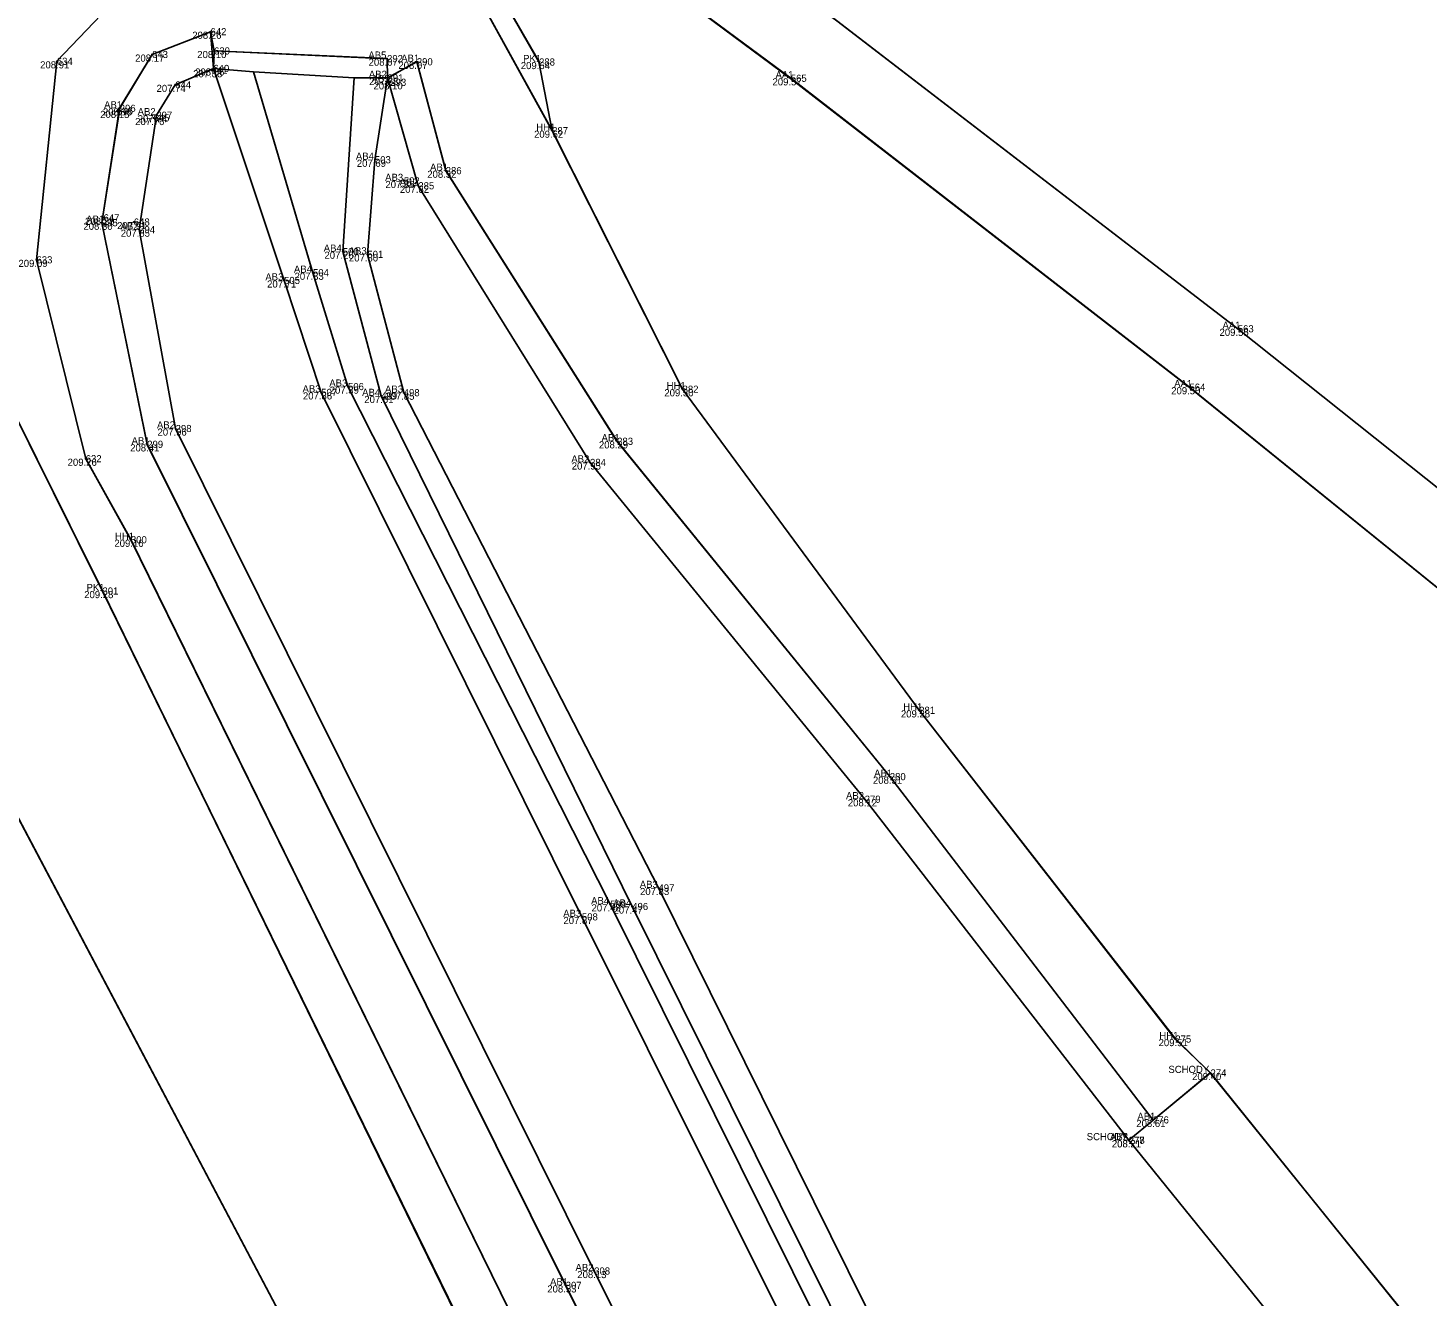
# Model space of a CAD drawing. Extents: x -262982 to -262706, y -1238714 to -1237093.
# Drawn here: x -262950.29 to -262911.03, y -1238449.49 to -1238413.92 of the extents above; entities that cross this region are included whole.
import ezdxf

# ---------------------------------------------------------------- set-up
doc = ezdxf.new("R2010")
doc.units = 0
for name, color, linetype in [('01_Hrana_betónu', 7, 'Continuous'), ('02_Oplotenie', 7, 'Continuous'), ('03_Asfalt', 7, 'Continuous'), ('05_Hrana_terénu', 7, 'Continuous'), ('06_Schody', 7, 'Continuous'), ('07_Iné', 7, 'Continuous'), ('10', 7, 'Continuous'), ('Groma (21)', 7, 'Continuous'), ('Groma (22)', 7, 'Continuous'), ('Groma (23)', 7, 'Continuous'), ('Groma (24)', 7, 'Continuous'), ('U001_Betónové_panely', 7, 'Continuous'), ('U001_Betóny_prídavné', 7, 'Continuous'), ('U001_Schody', 7, 'Continuous'), ('U001_Zeleň_mimo', 7, 'Continuous'), ('U001_Zeleň_vnútro', 7, 'Continuous'), ('U001_Zeleň_zatrávňovač', 7, 'Continuous'), ('U002_Asfalt', 7, 'Continuous'), ('U002_Zeleň_mimo', 7, 'Continuous')]:
    doc.layers.add(name, color=color, linetype=linetype)

msp = doc.modelspace()

# ---------------------------------------------------------------- linework, layer by layer
at = {"layer": '01_Hrana_betónu'}
for points in [[(-262945.17, -1238414.02), (-262946.81, -1238414.66), (-262947.715, -1238416.17), (-262948.218, -1238419.379), (-262946.945, -1238425.597), (-262935.208, -1238449.194), (-262927.854, -1238464.094), (-262916.808, -1238486.576), (-262907.486, -1238505.358), (-262899.299, -1238522.3), (-262896.198, -1238529.903), (-262891.697, -1238541.993), (-262882.447, -1238561.681), (-262873.377, -1238580.679), (-262868.934, -1238589.993), (-262864.101, -1238600.869)], [(-262863.262, -1238600.529), (-262868.088, -1238589.608), (-262872.609, -1238580.269), (-262881.626, -1238561.239), (-262890.834, -1238541.618), (-262895.354, -1238529.529), (-262898.372, -1238521.954), (-262906.659, -1238504.862), (-262915.915, -1238486.239), (-262927.038, -1238463.656), (-262934.41, -1238448.791), (-262946.148, -1238425.153), (-262947.17, -1238419.573), (-262946.689, -1238416.363), (-262946.16, -1238415.51), (-262945.09, -1238415.05), (-262945.17, -1238414.02)], [(-262919.416, -1238445.121), (-262926.823, -1238435.554), (-262934.526, -1238426.105), (-262939.342, -1238418.342), (-262940.205, -1238415.315), (-262939.384, -1238414.863)], [(-262939.384, -1238414.863), (-262938.574, -1238417.919), (-262933.765, -1238425.512), (-262926.119, -1238434.921), (-262918.733, -1238444.559)], [(-262945.09, -1238415.05), (-262943.108, -1238420.999), (-262942.065, -1238424.139), (-262934.754, -1238438.855), (-262923.683, -1238461.06), (-262913.753, -1238481.232), (-262903.896, -1238501.06), (-262894.759, -1238519.856), (-262890.317, -1238530.551), (-262883.158, -1238545.169), (-262873.572, -1238564.111), (-262869.728, -1238571.951), (-262860.562, -1238590.864), (-262854.835, -1238604.812), (-262840.38, -1238642.586), (-262833.174, -1238661.935), (-262826.575, -1238681.018), (-262825.738, -1238690.053), (-262824.527, -1238692.082)], [(-262821.464, -1238691.979), (-262823.978, -1238691.385), (-262824.893, -1238689.953), (-262825.729, -1238680.825), (-262832.468, -1238661.625), (-262839.672, -1238642.452), (-262854.271, -1238604.655), (-262859.863, -1238590.55), (-262868.949, -1238571.69), (-262872.864, -1238563.867), (-262882.403, -1238544.934), (-262889.591, -1238530.296), (-262894.035, -1238519.557), (-262903.102, -1238500.748), (-262912.912, -1238480.97), (-262922.987, -1238460.594), (-262933.962, -1238438.502), (-262941.314, -1238423.977), (-262942.296, -1238420.781), (-262943.962, -1238415.15)], [(-262941.142, -1238415.313), (-262941.461, -1238420.191), (-262940.383, -1238424.238), (-262933.343, -1238438.564), (-262922.27, -1238460.876), (-262912.449, -1238480.877), (-262902.557, -1238500.683), (-262893.416, -1238519.552), (-262889.058, -1238529.686), (-262881.962, -1238544.577), (-262872.106, -1238564.019), (-262868.478, -1238571.232), (-262859.211, -1238590.61), (-262852.998, -1238605.343), (-262846.933, -1238621.173), (-262838.559, -1238643.348), (-262831.894, -1238661.158), (-262825.164, -1238680.62), (-262824.312, -1238689.696), (-262823.847, -1238690.483), (-262822.763, -1238690.91), (-262821.486, -1238690.803)], [(-262821.555, -1238690.42), (-262822.731, -1238690.203), (-262823.426, -1238689.509), (-262824.318, -1238680.43), (-262831.163, -1238660.976), (-262837.946, -1238643.111), (-262846.365, -1238620.94), (-262852.333, -1238605.156), (-262858.618, -1238590.245), (-262867.784, -1238570.905), (-262871.416, -1238563.68), (-262881.223, -1238544.283), (-262888.392, -1238529.442), (-262892.626, -1238519.239), (-262901.725, -1238500.385), (-262911.6, -1238480.51), (-262921.479, -1238460.51), (-262932.607, -1238438.043), (-262939.752, -1238424.147), (-262940.771, -1238420.267), (-262940.559, -1238417.612), (-262940.205, -1238415.315)]]:
    msp.add_lwpolyline(points, dxfattribs=at)
at = {"layer": '02_Oplotenie'}
msp.add_lwpolyline([(-262935.956, -1238414.87), (-262937.48, -1238412.215), (-262943.77, -1238411.76), (-262954.62, -1238410.7), (-262953.69, -1238416.69), (-262950.95, -1238424.18), (-262948.2, -1238429.713), (-262938.076, -1238450.416), (-262931.824, -1238462.793)], dxfattribs=at)
at = {"layer": '03_Asfalt'}
for points in [[(-262913.444, -1238391.676), (-262911.985, -1238397.337), (-262910.006, -1238403.107), (-262907.769, -1238409.039), (-262901.709, -1238424.56), (-262896.942, -1238436.871), (-262897.547, -1238437.016), (-262898.706, -1238436.381), (-262904.848, -1238431.522), (-262916.36, -1238422.355), (-262927.608, -1238413.712), (-262940.472, -1238404.296), (-262944.235, -1238401.54), (-262944.94, -1238400.579), (-262945.063, -1238399.495), (-262942.635, -1238399.58), (-262939.962, -1238399.183), (-262936.84, -1238398.276), (-262934.121, -1238396.673), (-262931.78, -1238394.73), (-262927.567, -1238384.599)], [(-262974.83, -1238389.493), (-262966.434, -1238405.689), (-262952.335, -1238432.734), (-262942.188, -1238451.946), (-262934.983, -1238466.187), (-262921.957, -1238491.107), (-262911.861, -1238511.116), (-262905.822, -1238523.977), (-262900.647, -1238535.669), (-262888.764, -1238565.07), (-262881.2, -1238585.494), (-262874.644, -1238603.324)], [(-262842.406, -1238598.306), (-262850.452, -1238578.707), (-262858.82, -1238561.234), (-262870.509, -1238539), (-262873.344, -1238533.53), (-262876.375, -1238529.239), (-262880.031, -1238521.826), (-262869.115, -1238517.45), (-262870.175, -1238508.052), (-262871.319, -1238501.744), (-262886.895, -1238462.375), (-262895.067, -1238441.663), (-262905.824, -1238433.621), (-262917.716, -1238423.993), (-262928.896, -1238415.327), (-262941.774, -1238405.784), (-262954.673, -1238396.412), (-262962.054, -1238391.026)]]:
    msp.add_lwpolyline(points, dxfattribs=at)
at = {"layer": '05_Hrana_terénu'}
msp.add_lwpolyline([(-262927.783, -1238467.254), (-262930.465, -1238462.525), (-262936.779, -1238449.928), (-262947.402, -1238428.273), (-262948.67, -1238426), (-262950.05, -1238420.42), (-262949.48, -1238414.85), (-262946.99, -1238412.24), (-262943.77, -1238411.76), (-262937.85, -1238412.69), (-262935.589, -1238416.796), (-262931.931, -1238424.05), (-262925.295, -1238433.06), (-262918.113, -1238442.283), (-262917.125, -1238443.234)], dxfattribs=at)
at = {"layer": '06_Schody'}
msp.add_lwpolyline([(-262911.843, -1238449.792), (-262913.598, -1238450.895), (-262914.362, -1238451.375), (-262919.416, -1238445.121), (-262918.733, -1238444.559), (-262917.125, -1238443.234)], close=True, dxfattribs=at)
at = {"layer": '07_Iné'}
msp.add_lwpolyline([(-262945.07, -1238414.56), (-262945.09, -1238415.05), (-262945.09, -1238415.05), (-262943.962, -1238415.15), (-262941.142, -1238415.313), (-262940.205, -1238415.315), (-262940.205, -1238415.315), (-262940.219, -1238414.775)], close=True, dxfattribs=at)
at = {"layer": '10'}
msp.add_lwpolyline([(-262982.434, -1238375.977), (-262968.907, -1238386.238), (-262962.054, -1238391.026), (-262954.673, -1238396.412), (-262941.774, -1238405.784), (-262928.896, -1238415.327), (-262917.716, -1238423.993), (-262905.824, -1238433.621), (-262895.067, -1238441.663), (-262870.407, -1238460.6)], dxfattribs=at)
at = {"layer": 'Groma (21)'}
for centre in [(-262945.17, -1238414.02), (-262945.07, -1238414.56), (-262949.48, -1238414.85), (-262946.81, -1238414.66), (-262940.219, -1238414.775), (-262939.384, -1238414.863), (-262935.956, -1238414.87), (-262945.14, -1238415.1), (-262945.09, -1238415.05), (-262940.205, -1238415.315), (-262928.896, -1238415.327), (-262946.16, -1238415.51), (-262940.127, -1238415.44), (-262947.715, -1238416.17), (-262947.79, -1238416.24), (-262946.77, -1238416.44), (-262946.689, -1238416.363), (-262935.589, -1238416.796), (-262940.559, -1238417.612), (-262938.574, -1238417.919), (-262939.748, -1238418.206), (-262939.342, -1238418.342), (-262948.17, -1238419.24), (-262948.218, -1238419.379), (-262947.32, -1238419.36), (-262947.17, -1238419.573), (-262950.05, -1238420.42), (-262941.461, -1238420.191), (-262940.771, -1238420.267), (-262942.296, -1238420.781), (-262943.108, -1238420.999), (-262916.36, -1238422.355), (-262941.314, -1238423.977), (-262917.716, -1238423.993), (-262942.065, -1238424.139), (-262940.383, -1238424.238), (-262939.752, -1238424.147), (-262931.931, -1238424.05), (-262946.148, -1238425.153), (-262946.945, -1238425.597), (-262933.765, -1238425.512), (-262948.67, -1238426), (-262934.526, -1238426.105), (-262947.402, -1238428.273), (-262948.2, -1238429.713), (-262925.295, -1238433.06), (-262926.119, -1238434.921), (-262926.823, -1238435.554), (-262932.607, -1238438.043), (-262933.962, -1238438.502), (-262934.754, -1238438.855), (-262933.343, -1238438.564), (-262918.113, -1238442.283), (-262917.125, -1238443.234), (-262918.738, -1238444.552), (-262919.42, -1238445.124), (-262919.416, -1238445.121), (-262934.41, -1238448.791), (-262935.208, -1238449.194)]:
    msp.add_circle(centre, 0.01, dxfattribs=at)
at = {"layer": 'U001_Betónové_panely'}
msp.add_lwpolyline([(-262927.85, -1238464.09), (-262935.21, -1238449.19), (-262946.95, -1238425.6), (-262948.22, -1238419.38), (-262947.72, -1238416.17), (-262946.81, -1238414.66), (-262945.17, -1238414.02), (-262945.09, -1238415.05), (-262943.96, -1238415.15), (-262941.14, -1238415.31), (-262940.21, -1238415.32), (-262939.38, -1238414.86), (-262938.57, -1238417.92), (-262933.77, -1238425.51), (-262926.12, -1238434.92), (-262918.73, -1238444.56), (-262919.42, -1238445.12), (-262914.36, -1238451.38)], dxfattribs=at)
at = {"layer": 'U001_Betóny_prídavné'}
msp.add_lwpolyline([(-262943.96, -1238415.15), (-262945.09, -1238415.05), (-262945.07, -1238414.56), (-262940.22, -1238414.78), (-262940.21, -1238415.32), (-262941.14, -1238415.31)], close=True, dxfattribs=at)
at = {"layer": 'U001_Schody'}
msp.add_lwpolyline([(-262917.13, -1238443.23), (-262911.84, -1238449.79), (-262913.6, -1238450.89), (-262914.36, -1238451.38), (-262919.42, -1238445.12), (-262918.73, -1238444.56)], close=True, dxfattribs=at)
at = {"layer": 'U001_Zeleň_mimo'}
for points in [[(-262874.64, -1238603.32), (-262881.2, -1238585.49), (-262888.76, -1238565.07), (-262900.65, -1238535.67), (-262905.82, -1238523.98), (-262911.86, -1238511.12), (-262921.96, -1238491.11), (-262934.98, -1238466.19), (-262942.19, -1238451.95), (-262952.34, -1238432.73), (-262966.43, -1238405.69), (-262974.83, -1238389.49)], [(-262874.64, -1238603.32), (-262881.2, -1238585.49), (-262888.76, -1238565.07), (-262900.65, -1238535.67), (-262905.82, -1238523.98), (-262911.86, -1238511.12), (-262921.96, -1238491.11), (-262934.98, -1238466.19), (-262942.19, -1238451.95), (-262952.34, -1238432.73), (-262966.43, -1238405.69), (-262974.83, -1238389.49)], [(-262962.05, -1238391.03), (-262954.67, -1238396.41), (-262941.77, -1238405.78), (-262928.9, -1238415.33), (-262917.72, -1238423.99), (-262905.82, -1238433.62), (-262895.07, -1238441.66), (-262886.9, -1238462.38), (-262871.32, -1238501.74), (-262870.18, -1238508.05), (-262869.12, -1238517.45), (-262880.03, -1238521.83), (-262876.38, -1238529.24), (-262873.34, -1238533.53), (-262870.51, -1238539), (-262858.82, -1238561.23), (-262850.45, -1238578.71), (-262842.41, -1238598.31)], [(-262962.05, -1238391.03), (-262954.67, -1238396.41), (-262941.77, -1238405.78), (-262928.9, -1238415.33), (-262917.72, -1238423.99), (-262905.82, -1238433.62), (-262895.07, -1238441.66), (-262886.9, -1238462.38), (-262871.32, -1238501.74), (-262870.18, -1238508.05), (-262869.12, -1238517.45), (-262880.03, -1238521.83), (-262876.38, -1238529.24), (-262873.34, -1238533.53), (-262870.51, -1238539), (-262858.82, -1238561.23), (-262850.45, -1238578.71), (-262842.41, -1238598.31)], [(-262911.84, -1238449.79), (-262917.13, -1238443.23), (-262918.11, -1238442.28), (-262925.3, -1238433.06), (-262931.93, -1238424.05), (-262935.59, -1238416.8), (-262935.96, -1238414.87), (-262937.48, -1238412.22), (-262943.77, -1238411.76), (-262954.62, -1238410.7), (-262953.69, -1238416.69), (-262950.95, -1238424.18), (-262948.2, -1238429.71), (-262938.08, -1238450.42)]]:
    msp.add_lwpolyline(points, dxfattribs=at)
at = {"layer": 'U001_Zeleň_vnútro'}
msp.add_lwpolyline([(-262908.34, -1238509.94), (-262919.31, -1238488.27), (-262929.26, -1238468.08), (-262927.92, -1238467.26), (-262930.86, -1238463.25), (-262931.82, -1238462.79), (-262938.08, -1238450.42), (-262948.2, -1238429.71), (-262950.95, -1238424.18), (-262953.69, -1238416.69), (-262954.62, -1238410.7), (-262943.77, -1238411.76), (-262946.99, -1238412.24), (-262949.48, -1238414.85), (-262950.05, -1238420.42), (-262948.67, -1238426), (-262947.4, -1238428.27), (-262936.78, -1238449.93), (-262930.47, -1238462.53), (-262927.78, -1238467.25), (-262927.47, -1238468.81), (-262918.2, -1238487.16), (-262908.25, -1238507.59)], dxfattribs=at)
msp.add_lwpolyline([(-262935.59, -1238416.8), (-262937.85, -1238412.69), (-262943.77, -1238411.76), (-262937.48, -1238412.22), (-262935.96, -1238414.87)], close=True, dxfattribs=at)
at = {"layer": 'U001_Zeleň_zatrávňovač'}
for points in [[(-262936.78, -1238449.93), (-262947.4, -1238428.27), (-262948.67, -1238426), (-262950.05, -1238420.42), (-262949.48, -1238414.85), (-262946.99, -1238412.24)], [(-262937.85, -1238412.69), (-262935.59, -1238416.8), (-262931.93, -1238424.05), (-262925.3, -1238433.06), (-262918.11, -1238442.28), (-262917.13, -1238443.23), (-262918.73, -1238444.56), (-262926.12, -1238434.92), (-262933.77, -1238425.51), (-262938.57, -1238417.92), (-262939.38, -1238414.86), (-262940.21, -1238415.32), (-262940.22, -1238414.78), (-262945.07, -1238414.56), (-262945.17, -1238414.02), (-262946.81, -1238414.66), (-262947.72, -1238416.17), (-262948.22, -1238419.38), (-262946.95, -1238425.6), (-262935.21, -1238449.19), (-262927.85, -1238464.09)]]:
    msp.add_lwpolyline(points, dxfattribs=at)
at = {"layer": 'U002_Asfalt'}
msp.add_lwpolyline([(-262927.57, -1238384.6), (-262931.78, -1238394.73), (-262934.12, -1238396.67), (-262936.84, -1238398.28), (-262939.96, -1238399.18), (-262942.64, -1238399.58), (-262945.06, -1238399.5), (-262944.94, -1238400.58), (-262944.24, -1238401.54), (-262940.47, -1238404.3), (-262927.61, -1238413.71), (-262916.36, -1238422.36), (-262904.85, -1238431.52), (-262898.71, -1238436.38), (-262897.55, -1238437.02), (-262896.94, -1238436.87), (-262895.07, -1238441.66), (-262905.82, -1238433.62), (-262917.72, -1238423.99), (-262928.9, -1238415.33), (-262941.77, -1238405.78), (-262954.67, -1238396.41), (-262962.05, -1238391.03)], dxfattribs=at)
at = {"layer": 'U002_Zeleň_mimo'}
msp.add_lwpolyline([(-262913.44, -1238391.68), (-262911.99, -1238397.34), (-262910.01, -1238403.11), (-262907.77, -1238409.04), (-262901.71, -1238424.56), (-262896.94, -1238436.87), (-262897.55, -1238437.02), (-262898.71, -1238436.38), (-262904.85, -1238431.52), (-262916.36, -1238422.36), (-262927.61, -1238413.71), (-262940.47, -1238404.3), (-262944.24, -1238401.54), (-262944.94, -1238400.58), (-262945.06, -1238399.5), (-262942.64, -1238399.58), (-262939.96, -1238399.18), (-262936.84, -1238398.28), (-262934.12, -1238396.67), (-262931.78, -1238394.73), (-262927.57, -1238384.6)], dxfattribs=at)

# ---------------------------------------------------------------- texts
at = {"layer": 'Groma (22)'}
for s, p in [('642', (-262945.17, -1238414.12)), ('643', (-262946.81, -1238414.76)), ('639', (-262945.07, -1238414.66)), ('634', (-262949.48, -1238414.95)), ('640', (-262945.09, -1238415.15)), ('292', (-262940.219, -1238414.875)), ('290', (-262939.384, -1238414.963)), ('288', (-262935.956, -1238414.97)), ('641', (-262945.14, -1238415.2)), ('291', (-262940.205, -1238415.415)), ('293', (-262940.127, -1238415.54)), ('565', (-262928.896, -1238415.427)), ('644', (-262946.16, -1238415.61)), ('646', (-262947.79, -1238416.34)), ('296', (-262947.715, -1238416.27)), ('645', (-262946.77, -1238416.54)), ('297', (-262946.689, -1238416.463)), ('287', (-262935.589, -1238416.896)), ('503', (-262940.559, -1238417.712)), ('502', (-262939.748, -1238418.306)), ('286', (-262938.574, -1238418.019)), ('285', (-262939.342, -1238418.442)), ('295', (-262948.218, -1238419.479)), ('647', (-262948.17, -1238419.34)), ('648', (-262947.32, -1238419.46)), ('294', (-262947.17, -1238419.673)), ('500', (-262941.461, -1238420.291)), ('633', (-262950.05, -1238420.52)), ('501', (-262940.771, -1238420.367)), ('504', (-262942.296, -1238420.881)), ('505', (-262943.108, -1238421.099)), ('563', (-262916.36, -1238422.455)), ('506', (-262941.314, -1238424.077)), ('282', (-262931.931, -1238424.15)), ('564', (-262917.716, -1238424.093)), ('507', (-262942.065, -1238424.239)), ('499', (-262940.383, -1238424.338)), ('498', (-262939.752, -1238424.247)), ('298', (-262946.148, -1238425.253)), ('299', (-262946.945, -1238425.697)), ('283', (-262933.765, -1238425.612)), ('632', (-262948.67, -1238426.1)), ('284', (-262934.526, -1238426.205)), ('300', (-262947.402, -1238428.373)), ('301', (-262948.2, -1238429.813)), ('281', (-262925.295, -1238433.16)), ('280', (-262926.119, -1238435.021)), ('279', (-262926.823, -1238435.654)), ('497', (-262932.607, -1238438.143)), ('509', (-262933.962, -1238438.602)), ('496', (-262933.343, -1238438.664)), ('508', (-262934.754, -1238438.955)), ('275', (-262918.113, -1238442.383)), ('274', (-262917.125, -1238443.334)), ('276', (-262918.738, -1238444.652)), ('277', (-262919.42, -1238445.224)), ('278', (-262919.416, -1238445.221)), ('308', (-262934.41, -1238448.891)), ('307', (-262935.208, -1238449.294))]:
    msp.add_text(s, height=0.2, dxfattribs=at).set_placement(p)
at = {"layer": 'Groma (23)'}
for s, p in [('208.26', (-262945.682, -1238414.22)), ('208.10', (-262945.542, -1238414.76)), ('208.91', (-262949.948, -1238415.05)), ('208.17', (-262947.284, -1238414.86)), ('208.07', (-262940.736, -1238414.975)), ('208.07', (-262939.901, -1238415.063)), ('209.64', (-262936.468, -1238415.07)), ('207.58', (-262945.657, -1238415.3)), ('208.06', (-262945.601, -1238415.25)), ('207.63', (-262940.718, -1238415.515)), ('209.57', (-262929.409, -1238415.527)), ('207.74', (-262946.683, -1238415.71)), ('208.10', (-262940.599, -1238415.64)), ('208.18', (-262948.188, -1238416.37)), ('208.15', (-262948.263, -1238416.44)), ('207.76', (-262947.283, -1238416.64)), ('207.74', (-262947.212, -1238416.563)), ('209.62', (-262936.096, -1238416.996)), ('207.69', (-262941.067, -1238417.812)), ('208.32', (-262939.091, -1238418.119)), ('207.85', (-262940.265, -1238418.406)), ('207.82', (-262939.859, -1238418.542)), ('208.28', (-262948.687, -1238419.44)), ('208.30', (-262948.734, -1238419.579)), ('207.91', (-262947.789, -1238419.56)), ('207.85', (-262947.687, -1238419.773)), ('209.09', (-262950.556, -1238420.62)), ('207.26', (-262941.974, -1238420.391)), ('207.80', (-262941.288, -1238420.467)), ('207.33', (-262942.813, -1238420.981)), ('207.71', (-262943.583, -1238421.199)), ('209.55', (-262916.872, -1238422.555)), ('207.39', (-262941.827, -1238424.177)), ('209.50', (-262918.227, -1238424.193)), ('207.86', (-262942.578, -1238424.339)), ('207.51', (-262940.857, -1238424.438)), ('207.85', (-262940.269, -1238424.347)), ('209.30', (-262932.442, -1238424.25)), ('207.96', (-262946.656, -1238425.353)), ('208.41', (-262947.423, -1238425.797)), ('208.29', (-262934.277, -1238425.712)), ('209.26', (-262949.177, -1238426.2)), ('207.95', (-262935.039, -1238426.305)), ('209.16', (-262947.866, -1238428.473)), ('209.28', (-262948.712, -1238429.913)), ('209.28', (-262925.807, -1238433.26)), ('208.51', (-262926.592, -1238435.121)), ('208.12', (-262927.296, -1238435.754)), ('207.83', (-262933.124, -1238438.243)), ('207.48', (-262934.484, -1238438.702)), ('207.87', (-262935.272, -1238439.055)), ('207.47', (-262933.866, -1238438.764)), ('209.51', (-262918.581, -1238442.483)), ('209.40', (-262917.641, -1238443.434)), ('208.61', (-262919.206, -1238444.752)), ('208.21', (-262919.893, -1238445.324)), ('208.21', (-262919.889, -1238445.321)), ('208.13', (-262934.883, -1238448.991)), ('208.53', (-262935.725, -1238449.394))]:
    msp.add_text(s, height=0.2, dxfattribs=at).set_placement(p)
at = {"layer": 'Groma (24)'}
for s, p in [('AB5', (-262940.743, -1238414.775)), ('AB1', (-262939.822, -1238414.863)), ('PK1', (-262936.403, -1238414.87)), ('AB2', (-262940.729, -1238415.315)), ('AB5', (-262940.651, -1238415.44)), ('AA1', (-262929.324, -1238415.327)), ('AB1', (-262948.153, -1238416.17)), ('AB2', (-262947.213, -1238416.363)), ('HH1', (-262936.036, -1238416.796)), ('AB4', (-262941.093, -1238417.612)), ('AB1', (-262939.012, -1238417.919)), ('AB3', (-262940.272, -1238418.206)), ('AB2', (-262939.866, -1238418.342)), ('AB1', (-262948.656, -1238419.379)), ('AB2', (-262947.694, -1238419.573)), ('AB4', (-262941.995, -1238420.191)), ('AB3', (-262941.295, -1238420.267)), ('AB3', (-262943.632, -1238420.999)), ('AB4', (-262942.83, -1238420.781)), ('AA1', (-262916.788, -1238422.355)), ('AB3', (-262942.589, -1238424.139)), ('AB3', (-262941.838, -1238423.977)), ('AB3', (-262940.276, -1238424.147)), ('HH1', (-262932.378, -1238424.05)), ('AA1', (-262918.144, -1238423.993)), ('AB4', (-262940.917, -1238424.238)), ('AB2', (-262946.672, -1238425.153)), ('AB1', (-262947.383, -1238425.597)), ('AB1', (-262934.203, -1238425.512)), ('AB2', (-262935.05, -1238426.105)), ('HH1', (-262947.849, -1238428.273)), ('PK1', (-262948.647, -1238429.713)), ('HH1', (-262925.742, -1238433.06)), ('AB1', (-262926.557, -1238434.921)), ('AB2', (-262927.347, -1238435.554)), ('AB3', (-262933.131, -1238438.043)), ('AB4', (-262934.496, -1238438.502)), ('AB4', (-262933.877, -1238438.564)), ('AB3', (-262935.278, -1238438.855)), ('HH1', (-262918.56, -1238442.283)), ('SCHODY', (-262918.306, -1238443.234)), ('AB1', (-262919.176, -1238444.552)), ('SCHODY', (-262920.597, -1238445.121)), ('AB2', (-262919.944, -1238445.124)), ('AB2', (-262934.934, -1238448.791)), ('AB1', (-262935.646, -1238449.194))]:
    msp.add_text(s, height=0.2, dxfattribs=at).set_placement(p)

doc.saveas('drawing.dxf')
